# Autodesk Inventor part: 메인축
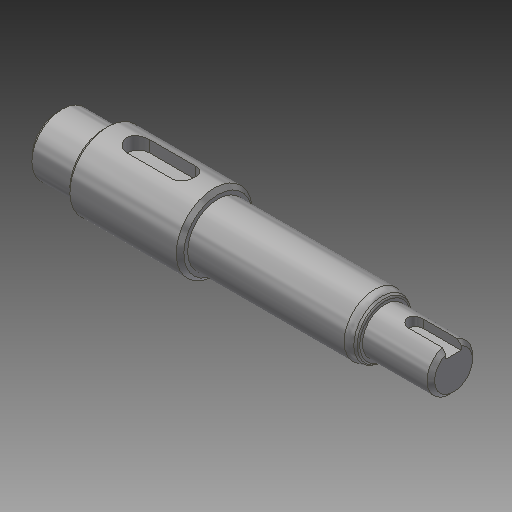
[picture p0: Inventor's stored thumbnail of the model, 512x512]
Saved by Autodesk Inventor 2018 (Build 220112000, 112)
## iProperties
Created: 2019-03
Part Number: 메인축
Material: 강철, 연강
Document SubType Name: Modeling
Designer: mduedu
Density: 1 g/cm^3
Appearance: 강철
Author: mduedu
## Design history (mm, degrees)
sketch "스케치1"
  geometry: L1 (0, 0)-(12, 0); L2 (12, 0)-(12, 8); L3 (12, 8)-(0, 8); L4 (0, 8)-(0, 0); L5 (12, 0)-(42, 0); L6 (42, 0)-(42, 10); L7 (42, 10)-(12, 10); L8 (12, 10)-(12, 0); L9 (42, 0)-(86, 0); L10 (86, 0)-(86, 8); L11 (86, 8)-(42, 8); L12 (42, 8)-(42, 0); L13 (86, 0)-(104, 0); L14 (104, 0)-(104, 6); L15 (104, 6)-(86, 6); L16 (86, 6)-(86, 0)
  constraints: 32 end point, 8 parallel, 4 horizontal, 4 perpendicular
  dimensions: "d0" = 16 diameter of L3 L1; "d2" = 20 diameter of L7 L5; "d3" = 16 diameter of L11 L9; "d4" = 12 diameter of L15 L13; "d5" = 12 distance of L2.end L3.end; "d6" = 30 distance of L6.end L7.end; "d7" = 86 distance between parallel lines of L10 L4; "d8" = 104 distance between parallel lines of L14 L4
revolve "회전1" sketch "스케치1" stored, may be unused: angle "d9" = 90 deg
node "작업 평면1"
sketch "스케치2" dims "d10" = 18
  geometry: L1 (6, -3)-(-6, -3); L2 (-6, -3)-(-6, 3); L3 (-6, 3)-(6, 3); L4 (6, 3)-(6, -3); L5 (15, 10)-(15, -10) reference; 3 further points
  constraints: 8 end point, 2 midpoint, 2 parallel, 2 vertical alignment, 1 horizontal, 1 horizontal alignment, 1 perpendicular, 4 other
  dimensions: "d12" = 6 distance between parallel lines of L3 L1; "d13" = 6 dimension on L5
extrude "돌출1" cut sketch "스케치2" distance "d14" = 3.5; taper "d15" = 0 deg
node "작업 평면2"
sketch "스케치3"
  geometry: L1 (-9, 6)-(-9, -6) reference; L2 (1, -2)-(-9, -2); L3 (1, 2)-(-9, 2); A1 r 2 centre (1, 0) between (1, -2) and (1, 2); 2 further points
  constraints: 4 end point, 2 point on circle, 2 point on line, 2 tangent, 1 centre point, 1 horizontal alignment, 1 midpoint, 1 parallel, 1 perpendicular
  dimensions: "d16" = 12 dimension on A1 L1; "d17" = 4 distance between parallel lines of L3 L2
extrude "돌출2" cut sketch "스케치3" distance "d18" = 2.5; taper "d19" = 0 deg
chamfer "모따기1" distance "d20" = 1; stored, may be unused: second distance "d21" = 2, angle "d22" = 45 deg
chamfer "모따기2" distance "d23" = 1; stored, may be unused: second distance "d24" = 2, angle "d25" = 45 deg
chamfer "모따기3" distance "d26" = 1.73; stored, may be unused: second distance "d27" = 2, angle "d28" = 30 deg
fillet "모깎기2" dims "d31" = 0.5, "d32" = 4
node "솔리드1"
